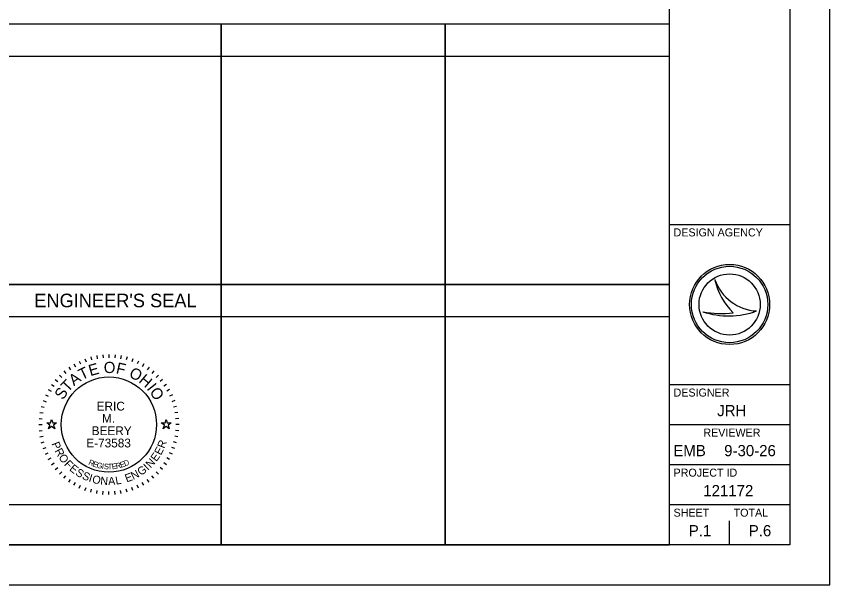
# Model space of a CAD drawing. Extents: x 0 to 40.2, y 0 to 22.
# Drawn here: x 23.84 to 34, y 0 to 7.1 of the extents above; entities that cross this region are included whole.
import ezdxf

# ---------------------------------------------------------------- set-up
doc = ezdxf.new("R2010")
doc.units = 0
for name, color, linetype in [('SH_Border', 7, 'Continuous'), ('SH_Cut_Line', 7, 'Continuous'), ('SH_Data', 7, 'Continuous'), ('SH_Seal', 7, 'Continuous')]:
    doc.layers.add(name, color=color, linetype=linetype)

msp = doc.modelspace()

# ---------------------------------------------------------------- linework, layer by layer
at = {"layer": 'SH_Border'}
for p, q in [((32, 0.5), (32, 21.5)), ((32, 4.5), (33.5, 4.5)), ((32, 2.5), (33.5, 2.5)), ((32, 2), (33.5, 2)), ((32, 1.5), (33.5, 1.5)), ((32, 1), (33.5, 1))]:
    msp.add_line(p, q, dxfattribs=at)
msp.add_lwpolyline([(1.5, 21.5), (33.5, 21.5), (33.5, 0.5), (1.5, 0.5)], close=True, dxfattribs=at)
at = {"layer": 'SH_Cut_Line'}
msp.add_lwpolyline([(0, 0), (34, 0), (34, 22), (0, 22)], close=True, dxfattribs=at)
at = {"layer": 'SH_Data'}
for p, q in [((23.6, 6.6), (26.4, 6.6)), ((26.4, 6.6), (29.2, 6.6)), ((29.2, 6.6), (32, 6.6)), ((32.567, 3.81), (32.567, 3.81)), ((23.6, 3.75), (26.4, 3.75)), ((26.4, 3.75), (26.4, 0.5)), ((32.75, 3.5), (32.75, 3.5)), ((32.417, 3.41), (32.417, 3.41)), ((33.087, 3.419), (33.087, 3.419)), ((23.6, 3.35), (26.4, 3.35)), ((23.6, 3.35), (26.4, 3.35)), ((26.4, 3.35), (29.2, 3.35)), ((29.2, 3.35), (32, 3.35)), ((32.75, 0.5), (32.75, 0.8)), ((32.375, 0.675), (32.375, 0.675)), ((23.6, 0.5), (26.4, 0.5))]:
    msp.add_line(p, q, dxfattribs=at)
for points in [[(26.4, 7), (23.6, 7), (23.6, 3.75), (26.4, 3.75)], [(29.2, 7), (26.4, 7), (26.4, 3.75), (29.2, 3.75)], [(32, 7), (29.2, 7), (29.2, 3.75), (32, 3.75)], [(26.4, 3.75), (23.6, 3.75), (23.6, 0.5), (26.4, 0.5)], [(29.2, 3.75), (26.4, 3.75), (26.4, 0.5), (29.2, 0.5)], [(32, 3.75), (29.2, 3.75), (29.2, 0.5), (32, 0.5)], [(23.6, 0.5), (23.6, 1), (26.4, 1), (26.4, 0.5)]]:
    msp.add_lwpolyline(points, close=True, dxfattribs=at)
for radius in [0.5, 0.477, 0.477, 0.382]:
    msp.add_circle((32.75, 3.5), radius, dxfattribs=at)
for centre, radius, start, end in [((33.116, 3.998), 0.58, 198.9257, 198.9319), ((33.347, 3.97), 0.796, 191.6379, 191.6421), ((33.116, 3.998), 0.58, 198.9319, 267.1657), ((33.347, 3.97), 0.796, 191.6421, 226.0947), ((32.739, 4.37), 1.013, 251.4576, 290.0832), ((32.648, 4.654), 1.266, 259.4964, 259.4995), ((32.739, 4.37), 1.013, 251.4527, 251.4576), ((32.648, 4.654), 1.266, 259.4995, 276.6672)]:
    msp.add_arc(centre, radius, start, end, dxfattribs=at)
at = {"layer": 'SH_Seal'}
for p, q in [((24.774, 2.845), (24.784, 2.807)), ((24.848, 2.862), (24.855, 2.822)), ((24.924, 2.872), (24.927, 2.832)), ((25, 2.875), (25, 2.835)), ((25.076, 2.872), (25.073, 2.832)), ((25.152, 2.862), (25.145, 2.822)), ((25.226, 2.845), (25.216, 2.807)), ((24.563, 2.758), (24.583, 2.723)), ((24.63, 2.793), (24.647, 2.757)), ((24.701, 2.822), (24.714, 2.785)), ((25.299, 2.822), (25.286, 2.785)), ((25.37, 2.793), (25.353, 2.757)), ((25.437, 2.758), (25.417, 2.723)), ((24.438, 2.67), (24.463, 2.64)), ((24.498, 2.717), (24.521, 2.684)), ((25.502, 2.717), (25.479, 2.684)), ((25.562, 2.67), (25.537, 2.64)), ((24.33, 2.562), (24.36, 2.537)), ((24.381, 2.619), (24.41, 2.59)), ((25.619, 2.619), (25.59, 2.59)), ((25.67, 2.562), (25.64, 2.537)), ((24.283, 2.502), (24.316, 2.479)), ((25.717, 2.502), (25.684, 2.479)), ((24.207, 2.37), (24.243, 2.353)), ((24.242, 2.438), (24.277, 2.418)), ((25.758, 2.438), (25.723, 2.418)), ((25.793, 2.37), (25.757, 2.353)), ((24.178, 2.299), (24.215, 2.286)), ((25.822, 2.299), (25.785, 2.286)), ((24.138, 2.152), (24.178, 2.145)), ((24.155, 2.226), (24.193, 2.216)), ((25.845, 2.226), (25.807, 2.216)), ((25.862, 2.152), (25.822, 2.145)), ((24.128, 2.076), (24.168, 2.073)), ((25.872, 2.076), (25.832, 2.073)), ((24.125, 2), (24.165, 2)), ((25.875, 2), (25.835, 2)), ((24.128, 1.924), (24.168, 1.927)), ((24.138, 1.848), (24.178, 1.855)), ((25.862, 1.848), (25.822, 1.855)), ((25.872, 1.924), (25.832, 1.927)), ((24.155, 1.774), (24.193, 1.784)), ((25.845, 1.774), (25.807, 1.784)), ((24.178, 1.701), (24.215, 1.714)), ((24.207, 1.63), (24.243, 1.647)), ((25.793, 1.63), (25.757, 1.647)), ((25.822, 1.701), (25.785, 1.714)), ((24.242, 1.563), (24.277, 1.583)), ((25.758, 1.563), (25.723, 1.583)), ((24.283, 1.498), (24.316, 1.521)), ((24.33, 1.438), (24.36, 1.463)), ((25.67, 1.438), (25.64, 1.463)), ((25.717, 1.498), (25.684, 1.521)), ((24.381, 1.381), (24.41, 1.41)), ((24.438, 1.33), (24.463, 1.36)), ((25.562, 1.33), (25.537, 1.36)), ((25.619, 1.381), (25.59, 1.41)), ((24.498, 1.283), (24.521, 1.316)), ((24.563, 1.242), (24.583, 1.277)), ((24.63, 1.207), (24.647, 1.243)), ((25.37, 1.207), (25.353, 1.243)), ((25.437, 1.242), (25.417, 1.277)), ((25.502, 1.283), (25.479, 1.316)), ((24.701, 1.178), (24.714, 1.215)), ((24.774, 1.155), (24.784, 1.193)), ((24.848, 1.138), (24.855, 1.178)), ((24.924, 1.128), (24.927, 1.168)), ((25, 1.125), (25, 1.165)), ((25.076, 1.128), (25.073, 1.168)), ((25.152, 1.138), (25.145, 1.178)), ((25.226, 1.155), (25.216, 1.193)), ((25.299, 1.178), (25.286, 1.215))]:
    msp.add_line(p, q, dxfattribs=at)
for points in [[(24.224, 2.02), (24.271, 2.02), (24.285, 2.065), (24.299, 2.02), (24.346, 2.02), (24.308, 1.992), (24.323, 1.948), (24.285, 1.975), (24.247, 1.948), (24.262, 1.992)], [(25.654, 2.02), (25.701, 2.02), (25.715, 2.065), (25.729, 2.02), (25.776, 2.02), (25.738, 1.992), (25.753, 1.948), (25.715, 1.975), (25.677, 1.948), (25.692, 1.992)]]:
    msp.add_lwpolyline(points, close=True, dxfattribs=at)
msp.add_circle((25, 2), 0.595, dxfattribs=at)

# ---------------------------------------------------------------- texts
at = {"layer": 'SH_Data'}
for s, height, p in [('DESIGN AGENCY', 0.1, (32.05, 4.35)), ("ENGINEER'S SEAL", 0.17, (24.068, 3.465)), ('DESIGNER', 0.1, (32.05, 2.35)), ('JRH', 0.14, (32.595, 2.105)), ('REVIEWER', 0.1, (32.422, 1.85)), ('EMB', 0.14, (32.047, 1.605)), ('9-30-26', 0.14, (32.682, 1.605)), ('PROJECT ID', 0.1, (32.05, 1.35)), ('121172', 0.14, (32.421, 1.105)), ('SHEET', 0.1, (32.05, 0.85)), ('TOTAL', 0.1, (32.8, 0.85)), ('P.1', 0.14, (32.24, 0.605)), ('P.6', 0.14, (32.989, 0.605))]:
    msp.add_text(s, height=height, dxfattribs=at).set_placement(p)
at = {"layer": 'SH_Seal'}
for s, height, rotation, p in [('E', 0.14, 15.7571, (24.768, 2.604)), ('O', 0.14, 359.7812, (24.935, 2.644)), ('F', 0.14, 347.4362, (25.081, 2.642)), ('T', 0.14, 25.7167, (24.662, 2.552)), ('O', 0.14, 332.2586, (25.24, 2.602)), ('T', 0.14, 46.4344, (24.488, 2.396)), ('A', 0.14, 36.4747, (24.563, 2.478)), ('H', 0.14, 319.9136, (25.363, 2.536)), ('S', 0.14, 57.1924, (24.428, 2.301)), ('I', 0.14, 308.367, (25.466, 2.448)), ('O', 0.14, 303.1491, (25.502, 2.409)), ('P', 0.1, 291.494, (24.282, 1.762)), ('E', 0.1, 61.9951, (25.648, 1.61)), ('R', 0.1, 69.2322, (25.692, 1.695)), ('R', 0.1, 298.7311, (24.319, 1.672)), ('O', 0.1, 306.4666, (24.365, 1.588)), ('E', 0.1, 54.758, (25.593, 1.531)), ('F', 0.1, 314.7068, (24.434, 1.498)), ('R', 0.07, 334.487, (24.737, 1.505)), ('E', 0.07, 341.04, (24.791, 1.48)), ('G', 0.07, 347.4752, (24.841, 1.462)), ('R', 0.07, 11.9184, (25.092, 1.447)), ('E', 0.07, 17.6836, (25.15, 1.46)), ('D', 0.07, 23.3052, (25.201, 1.477)), ('N', 0.1, 47.0224, (25.52, 1.451)), ('E', 0.1, 321.4393, (24.498, 1.435)), ('S', 0.1, 328.6764, (24.574, 1.375)), ('I', 0.07, 353.7858, (24.909, 1.447)), ('S', 0.07, 356.8926, (24.936, 1.443)), ('T', 0.07, 3.0061, (24.986, 1.439)), ('E', 0.07, 6.0117, (25.039, 1.441)), ('N', 0.1, 27.3113, (25.304, 1.308)), ('G', 0.1, 35.0469, (25.398, 1.357)), ('I', 0.1, 43.287, (25.487, 1.421)), ('S', 0.1, 335.9134, (24.656, 1.327)), ('I', 0.1, 343.1505, (24.741, 1.29)), ('O', 0.1, 346.8859, (24.784, 1.275)), ('N', 0.1, 355.1261, (24.889, 1.252)), ('A', 0.1, 2.8617, (24.992, 1.244)), ('L', 0.1, 10.0987, (25.089, 1.249)), ('E', 0.1, 20.0742, (25.221, 1.277))]:
    msp.add_text(s, height=height, rotation=rotation, dxfattribs=at).set_placement(p)
for s, p in [('ERIC', (24.847, 2.175)), ('M.', (24.913, 2.022)), ('BEERY', (24.785, 1.868)), ('E-73583', (24.718, 1.715))]:
    msp.add_text(s, height=0.11, dxfattribs=at).set_placement(p)

doc.saveas('drawing.dxf')
